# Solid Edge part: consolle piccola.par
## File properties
Last saved by: i.fialdini
Revision: 62
Tipo di contenuto documento: 0
Accuracy: 0.990
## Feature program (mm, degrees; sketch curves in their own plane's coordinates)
body "unnamed Body 1"
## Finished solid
Body 1: solid body, 12 faces, 24 edges, 16 vertices.
  Faces by surface: spline 8, cylinder 4
  Edges by curve: circle 24
Bounding box of the edges (mm; curved faces can reach further): 595.000 x 446.000 x 21.000, from (-340.5, -939.1568, 681.9818) to (254.5, -493.1568, 702.9818).
Cylindrical faces by radius (mm): R10.5 x4
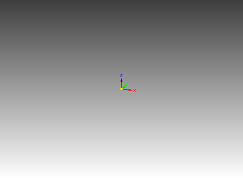
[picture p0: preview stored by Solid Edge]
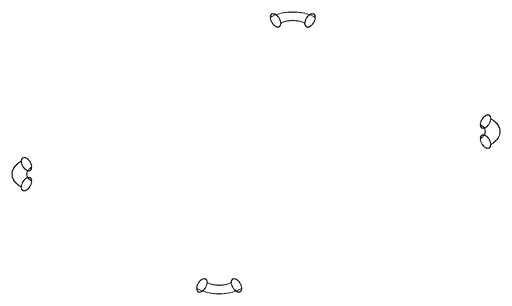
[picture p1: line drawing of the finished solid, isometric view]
